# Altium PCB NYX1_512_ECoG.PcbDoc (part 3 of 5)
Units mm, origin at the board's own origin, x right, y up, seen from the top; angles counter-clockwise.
Board outline 46.64 x 13 mm, 4 copper layers (metal 2, via, metal1, electrodes), stack 0.007 mm thick; 9 components, 547 nets, 1871 pads, 0 vias.
Unrouted connection lines stored in the file: 652.
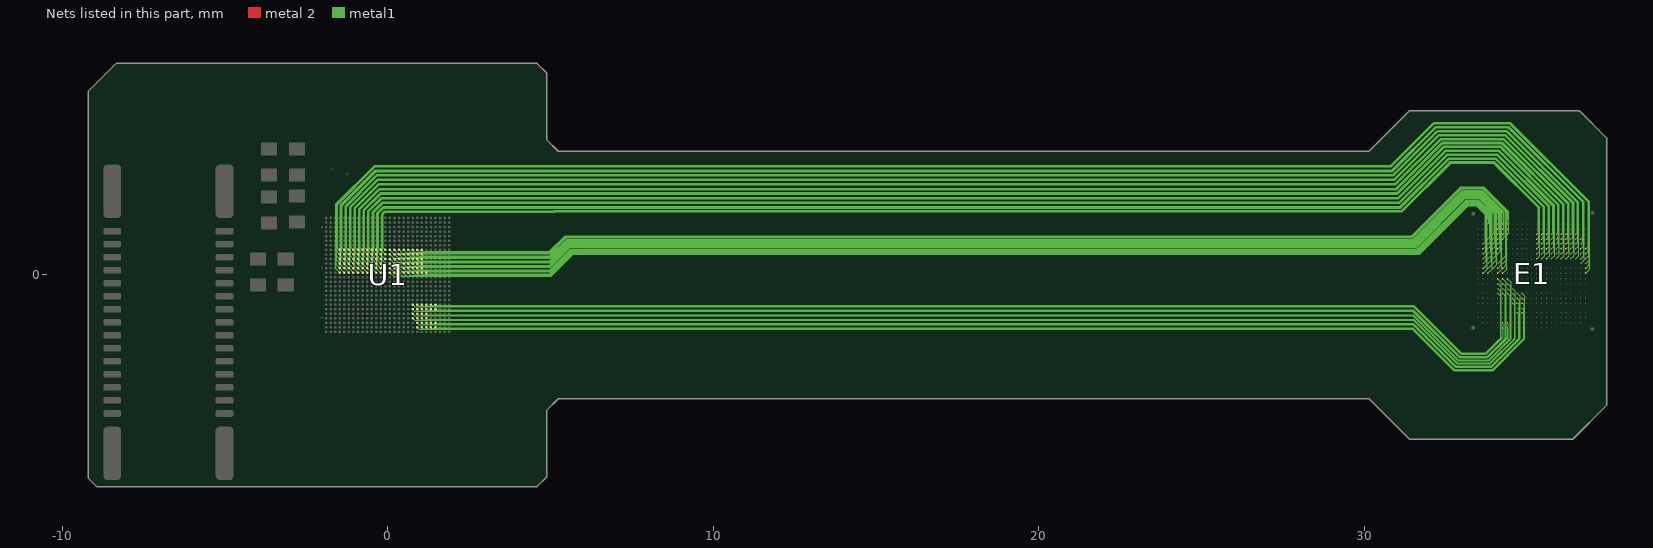
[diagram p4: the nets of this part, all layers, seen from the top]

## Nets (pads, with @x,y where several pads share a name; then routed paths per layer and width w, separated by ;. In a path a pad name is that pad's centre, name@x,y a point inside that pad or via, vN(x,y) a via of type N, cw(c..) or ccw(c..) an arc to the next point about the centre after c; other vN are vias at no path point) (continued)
el141: E1.21 pad.34@33.791,1.564 U1.F13 | length 34
  metal 2 w0.012: E1.21@33.791,1.544 pad.34@33.791,1.564
  metal1 w0.005: U1.F13@1.19,0.071 1.227,0.034 4.987,0.034 5.666,0.712 31.663,0.712 33.163,2.212 33.462,2.212 33.821,1.854 33.821,1.594 pad.34@33.791,1.564
el142: E1.70 pad.34@34.391,1.264 U1.G8 | length 35.3
  metal 2 w0.012: E1.70@34.391,1.244 pad.34@34.391,1.264
  metal1 w0.005: U1.G8@1.05,0.771 1.097,0.724 4.966,0.724 5.455,1.213 30.141,1.213 31.456,1.213 32.956,2.713 33.669,2.713 34.441,1.941 34.441,1.294 34.41,1.264 pad.34@34.391,1.264
el143: E1.92 pad.34@34.241,1.114 U1.G9 | length 35.3
  metal 2 w0.012: E1.92@34.241,1.094 pad.34@34.241,1.114
  metal1 w0.005: U1.G9@1.05,0.631 1.097,0.584 4.984,0.584 5.503,1.103 6.137,1.103 30.141,1.103 31.501,1.103 33.001,2.603 33.623,2.603 34.301,1.925 34.301,1.154 34.26,1.114 pad.34@34.241,1.114
el144: E1.160 pad.34@34.091,0.664 U1.G10 | length 35.6
  metal 2 w0.012: E1.160@34.091,0.644 pad.34@34.091,0.664
  metal1 w0.005: U1.G10@1.05,0.491 1.097,0.444 4.973,0.444 5.541,1.013 30.141,1.013 31.539,1.013 33.039,2.513 33.586,2.513 34.181,1.918 34.181,0.734 34.11,0.664 pad.34@34.091,0.664
el145: E1.228 pad.34@33.941,0.214 U1.G11 | length 35.9
  metal 2 w0.012: E1.228@33.941,0.194 pad.34@33.941,0.214
  metal1 w0.005: U1.G11@1.05,0.351 1.097,0.304 4.96,0.304 5.579,0.923 6.137,0.923 30.071,0.923 31.576,0.923 33.076,2.423 33.549,2.423 34.061,1.911 34.061,0.314 33.96,0.214 pad.34@33.941,0.214
el146: E1.250 pad.34@33.791,0.064 U1.G12 | length 35.9
  metal 2 w0.012: E1.250@33.791,0.044 pad.34@33.791,0.064
  metal1 w0.005: U1.G12@1.05,0.211 1.097,0.164 4.976,0.164 5.624,0.813 31.621,0.813 33.121,2.313 33.503,2.313 33.921,1.895 33.921,0.174 33.81,0.064 pad.34@33.791,0.064
el147: E1.1 pad.34@33.791,1.714 U1.G13 | length 34
  metal 2 w0.012: E1.1@33.791,1.694 pad.34@33.791,1.714
  metal1 w0.005: U1.G13@1.05,0.071 1.097,0.024 4.991,0.024 5.67,0.702 31.667,0.702 33.167,2.202 33.458,2.202 33.811,1.849 33.811,1.734 pad.34@33.791,1.714
el148: E1.47 pad.34@34.391,1.414 U1.H8 | length 35.3
  metal 2 w0.012: E1.47@34.391,1.394 pad.34@34.391,1.414
  metal1 w0.005: U1.H8@0.91,0.771 0.967,0.714 4.971,0.714 5.459,1.203 30.141,1.203 31.46,1.203 32.96,2.703 33.665,2.703 34.431,1.937 34.431,1.434 34.41,1.414 pad.34@34.391,1.414
el149: E1.69 pad.34@34.241,1.264 U1.H9 | length 35.2
  metal 2 w0.012: E1.69@34.241,1.244 pad.34@34.241,1.264
  metal1 w0.005: U1.H9@0.91,0.631 0.967,0.574 4.988,0.574 5.507,1.093 30.141,1.093 31.505,1.093 33.005,2.593 33.619,2.593 34.291,1.921 34.291,1.294 34.26,1.264 pad.34@34.241,1.264
el150: E1.137 pad.34@34.091,0.814 U1.H10 | length 35.5
  metal 2 w0.012: E1.137@34.091,0.794 pad.34@34.091,0.814
  metal1 w0.005: U1.H10@0.91,0.491 0.967,0.434 4.977,0.434 5.545,1.003 30.141,1.003 31.543,1.003 33.043,2.503 33.582,2.503 34.171,1.914 34.171,0.874 34.11,0.814 pad.34@34.091,0.814
el151: E1.205 pad.34@33.941,0.364 U1.H11 | length 35.9
  metal 2 w0.012: E1.205@33.941,0.344 pad.34@33.941,0.364
  metal1 w0.005: U1.H11@0.91,0.351 0.967,0.294 4.964,0.294 5.583,0.913 6.137,0.913 30.075,0.913 31.58,0.913 33.08,2.413 33.545,2.413 34.051,1.907 34.051,0.454 33.96,0.364 pad.34@33.941,0.364
el152: E1.227 pad.34@33.791,0.214 U1.H12 | length 35.8
  metal 2 w0.012: E1.227@33.791,0.194 pad.34@33.791,0.214
  metal1 w0.005: U1.H12@0.91,0.211 0.967,0.154 4.98,0.154 5.628,0.803 31.626,0.803 33.126,2.303 33.499,2.303 33.911,1.891 33.911,0.314 33.81,0.214 pad.34@33.791,0.214
el153: E1.249 pad.34@33.641,0.064 U1.H13 | length 35.8
  metal 2 w0.012: E1.249@33.641,0.044 pad.34@33.641,0.064
  metal1 w0.005: U1.H13@0.91,0.071 0.967,0.014 4.995,0.014 5.674,0.692 31.671,0.692 33.171,2.192 33.454,2.192 33.771,1.875 33.771,0.174 33.66,0.064 pad.34@33.641,0.064
el154: E1.25 pad.34@34.391,1.564 U1.J8 | length 35.2
  metal 2 w0.012: E1.25@34.391,1.544 pad.34@34.391,1.564
  metal1 w0.005: U1.J8@0.77,0.771 0.837,0.704 4.975,0.704 5.463,1.193 31.464,1.193 32.964,2.693 33.661,2.693 34.421,1.933 34.421,1.594 pad.34@34.391,1.564
el155: E1.46 pad.34@34.241,1.414 U1.J9 | length 35.2
  metal 2 w0.012: E1.46@34.241,1.394 pad.34@34.241,1.414
  metal1 w0.005: U1.J9@0.77,0.631 0.837,0.564 4.992,0.564 5.511,1.083 30.141,1.083 31.51,1.083 33.01,2.583 33.615,2.583 34.281,1.917 34.281,1.434 34.26,1.414 pad.34@34.241,1.414
el156: E1.114 pad.34@34.091,0.964 U1.J10 | length 35.5
  metal 2 w0.012: E1.114@34.091,0.944 pad.34@34.091,0.964
  metal1 w0.005: U1.J10@0.77,0.491 0.837,0.424 4.981,0.424 5.55,0.993 30.141,0.993 31.547,0.993 33.047,2.493 33.578,2.493 34.161,1.91 34.161,1.014 34.11,0.964 pad.34@34.091,0.964
el157: E1.182 pad.34@33.941,0.514 U1.J11 | length 35.8
  metal 2 w0.012: E1.182@33.941,0.494 pad.34@33.941,0.514
  metal1 w0.005: U1.J11@0.77,0.351 0.837,0.284 4.968,0.284 5.587,0.903 6.137,0.903 30.079,0.903 31.584,0.903 33.084,2.403 33.541,2.403 34.041,1.902 34.041,0.594 33.96,0.514 pad.34@33.941,0.514
el158: E1.204 pad.34@33.791,0.364 U1.J12 | length 35.8
  metal 2 w0.012: E1.204@33.791,0.344 pad.34@33.791,0.364
  metal1 w0.005: U1.J12@0.77,0.211 0.837,0.144 4.984,0.144 5.632,0.793 31.63,0.793 33.13,2.293 33.495,2.293 33.901,1.887 33.901,0.454 33.81,0.364 pad.34@33.791,0.364
el159: E1.226 pad.34@33.641,0.214 U1.J13 | length 35.8
  metal 2 w0.012: E1.226@33.641,0.194 pad.34@33.641,0.214
  metal1 w0.005: U1.J13@0.77,0.071 0.837,0.004 4.999,0.004 5.678,0.682 31.675,0.682 33.175,2.182 33.449,2.182 33.761,1.871 33.761,0.314 33.66,0.214 pad.34@33.641,0.214
el160: E1.5 pad.34@34.391,1.714 U1.K8 | length 35.2
  metal 2 w0.012: E1.5@34.391,1.694 pad.34@34.391,1.714
  metal1 w0.005: U1.K8@0.63,0.771 0.707,0.694 4.979,0.694 5.468,1.183 30.141,1.183 31.468,1.183 32.968,2.683 33.657,2.683 34.411,1.928 34.411,1.734 pad.34@34.391,1.714
el161: E1.24 pad.34@34.241,1.564 U1.K9 | length 35.2
  metal 2 w0.012: E1.24@34.241,1.544 pad.34@34.241,1.564
  metal1 w0.005: U1.K9@0.63,0.631 0.707,0.554 4.996,0.554 5.515,1.073 30.141,1.073 31.514,1.073 33.014,2.573 33.611,2.573 34.271,1.913 34.271,1.594 pad.34@34.241,1.564
el162: E1.91 pad.34@34.091,1.114 U1.K10 | length 35.5
  metal 2 w0.012: E1.91@34.091,1.094 pad.34@34.091,1.114
  metal1 w0.005: U1.K10@0.63,0.491 0.707,0.414 4.985,0.414 5.554,0.983 30.141,0.983 31.551,0.983 33.051,2.483 33.574,2.483 34.151,1.906 34.151,1.154 34.11,1.114 pad.34@34.091,1.114
el163: E1.159 pad.34@33.941,0.664 U1.K11 | length 35.8
  metal 2 w0.012: E1.159@33.941,0.644 pad.34@33.941,0.664
  metal1 w0.005: U1.K11@0.63,0.351 0.707,0.274 4.972,0.274 5.591,0.893 6.137,0.893 30.083,0.893 31.588,0.893 33.088,2.393 33.536,2.393 34.031,1.898 34.031,0.734 33.96,0.664 pad.34@33.941,0.664
el164: E1.181 pad.34@33.791,0.514 U1.K12 | length 35.8
  metal 2 w0.012: E1.181@33.791,0.494 pad.34@33.791,0.514
  metal1 w0.005: U1.K12@0.63,0.211 0.707,0.134 4.988,0.134 5.637,0.783 31.634,0.783 33.134,2.283 33.491,2.283 33.891,1.883 33.891,0.594 33.81,0.514 pad.34@33.791,0.514
el165: E1.203 pad.34@33.641,0.364 U1.K13 | length 35.8
  metal 2 w0.012: E1.203@33.641,0.344 pad.34@33.641,0.364
  metal1 w0.005: U1.K13@0.63,0.071 0.707,-0.006 5.004,-0.006 5.682,0.672 31.679,0.672 33.179,2.172 33.445,2.172 33.751,1.867 33.751,0.454 33.66,0.364 pad.34@33.641,0.364
el166: E1.253 pad.34@34.241,0.064 U1.L8 | length 37
  metal 2 w0.012: E1.253@34.241,0.044 pad.34@34.241,0.064
  metal1 w0.005: U1.L8@0.49,0.771 0.577,0.684 4.983,0.684 5.472,1.173 30.141,1.173 31.472,1.173 32.972,2.673 33.652,2.673 34.371,1.954 34.371,0.174 34.26,0.064 pad.34@34.241,0.064
el167: E1.4 pad.34@34.241,1.714 U1.L9 | length 35.1
  metal 2 w0.012: E1.4@34.241,1.694 pad.34@34.241,1.714
  metal1 w0.005: U1.L9@0.49,0.631 0.577,0.544 5.001,0.544 5.519,1.063 30.141,1.063 31.518,1.063 33.018,2.563 33.607,2.563 34.261,1.909 34.261,1.734 pad.34@34.241,1.714
el168: E1.68 pad.34@34.091,1.264 U1.L10 | length 35.5
  metal 2 w0.012: E1.68@34.091,1.244 pad.34@34.091,1.264
  metal1 w0.005: U1.L10@0.49,0.491 0.577,0.404 4.989,0.404 5.558,0.973 30.141,0.973 31.555,0.973 33.055,2.473 33.57,2.473 34.141,1.901 34.141,1.294 34.11,1.264 pad.34@34.091,1.264
el169: E1.136 pad.34@33.941,0.814 U1.L11 | length 35.8
  metal 2 w0.012: E1.136@33.941,0.794 pad.34@33.941,0.814
  metal1 w0.005: U1.L11@0.49,0.351 0.577,0.264 4.976,0.264 5.595,0.883 6.137,0.883 30.087,0.883 31.592,0.883 33.092,2.383 33.532,2.383 34.021,1.894 34.021,0.874 33.96,0.814 pad.34@33.941,0.814
el170: E1.158 pad.34@33.791,0.664 U1.L12 | length 35.8
  metal 2 w0.012: E1.158@33.791,0.644 pad.34@33.791,0.664
  metal1 w0.005: U1.L12@0.49,0.211 0.577,0.124 4.992,0.124 5.641,0.773 31.638,0.773 33.138,2.273 33.487,2.273 33.881,1.878 33.881,0.734 33.81,0.664 pad.34@33.791,0.664
el171: E1.180 pad.34@33.641,0.514 U1.L13 | length 35.7
  metal 2 w0.012: E1.180@33.641,0.494 pad.34@33.641,0.514
  metal1 w0.005: U1.L13@0.49,0.071 0.577,-0.016 5.008,-0.016 5.686,0.662 31.684,0.662 33.184,2.162 33.441,2.162 33.741,1.863 33.741,0.594 33.66,0.514 pad.34@33.641,0.514
el172: E1.230 pad.34@34.241,0.214 U1.M8 | length 37
  metal 2 w0.012: E1.230@34.241,0.194 pad.34@34.241,0.214
  metal1 w0.005: U1.M8@0.35,0.771 0.447,0.674 4.987,0.674 5.476,1.163 30.141,1.163 31.476,1.163 32.976,2.663 33.648,2.663 34.361,1.95 34.361,0.314 34.26,0.214 pad.34@34.241,0.214
el173: E1.252 pad.34@34.091,0.064 U1.M9 | length 37
  metal 2 w0.012: E1.252@34.091,0.044 pad.34@34.091,0.064
  metal1 w0.005: U1.M9@0.35,0.631 0.447,0.534 5.005,0.534 5.523,1.053 30.141,1.053 31.522,1.053 33.022,2.553 33.603,2.553 34.221,1.935 34.221,0.174 34.11,0.064 pad.34@34.091,0.064
el174: E1.45 pad.34@34.091,1.414 U1.M10 | length 35.4
  metal 2 w0.012: E1.45@34.091,1.394 pad.34@34.091,1.414
  metal1 w0.005: U1.M10@0.35,0.491 0.447,0.394 4.993,0.394 5.562,0.963 30.141,0.963 31.559,0.963 33.059,2.463 33.565,2.463 34.131,1.897 34.131,1.434 34.11,1.414 pad.34@34.091,1.414
el175: E1.113 pad.34@33.941,0.964 U1.M11 | length 35.8
  metal 2 w0.012: E1.113@33.941,0.944 pad.34@33.941,0.964
  metal1 w0.005: U1.M11@0.35,0.351 0.447,0.254 4.981,0.254 5.599,0.873 6.137,0.873 30.091,0.873 31.597,0.873 33.097,2.373 33.528,2.373 34.011,1.89 34.011,1.014 33.96,0.964 pad.34@33.941,0.964
el176: E1.135 pad.34@33.791,0.814 U1.M12 | length 35.7
  metal 2 w0.012: E1.135@33.791,0.794 pad.34@33.791,0.814
  metal1 w0.005: U1.M12@0.35,0.211 0.447,0.114 4.996,0.114 5.645,0.763 31.642,0.763 33.142,2.263 33.483,2.263 33.871,1.874 33.871,0.874 33.81,0.814 pad.34@33.791,0.814
el177: E1.157 pad.34@33.641,0.664 U1.M13 | length 35.7
  metal 2 w0.012: E1.157@33.641,0.644 pad.34@33.641,0.664
  metal1 w0.005: U1.M13@0.35,0.071 0.447,-0.026 5.012,-0.026 5.69,0.652 31.688,0.652 33.188,2.152 33.437,2.152 33.731,1.859 33.731,0.734 33.66,0.664 pad.34@33.641,0.664
el178: E1.207 pad.34@34.241,0.364 U1.N8 | length 37
  metal 2 w0.012: E1.207@34.241,0.344 pad.34@34.241,0.364
  metal1 w0.005: U1.N8@0.21,0.771 0.317,0.664 4.991,0.664 5.48,1.153 30.141,1.153 31.481,1.153 32.981,2.653 33.644,2.653 34.351,1.946 34.351,0.454 34.26,0.364 pad.34@34.241,0.364
el179: E1.229 pad.34@34.091,0.214 U1.N9 | length 36.9
  metal 2 w0.012: E1.229@34.091,0.194 pad.34@34.091,0.214
  metal1 w0.005: U1.N9@0.21,0.631 0.317,0.524 5.009,0.524 5.528,1.043 30.141,1.043 31.526,1.043 33.026,2.543 33.599,2.543 34.211,1.93 34.211,0.314 34.11,0.214 pad.34@34.091,0.214
el180: E1.23 pad.34@34.091,1.564 U1.N10 | length 35.4
  metal 2 w0.012: E1.23@34.091,1.544 pad.34@34.091,1.564
  metal1 w0.005: U1.N10@0.21,0.491 0.317,0.384 4.997,0.384 5.566,0.953 6.137,0.953 30.058,0.953 31.563,0.953 33.063,2.453 33.561,2.453 34.121,1.893 34.121,1.594 pad.34@34.091,1.564
el181: E1.90 pad.34@33.941,1.114 U1.N11 | length 35.7
  metal 2 w0.012: E1.90@33.941,1.094 pad.34@33.941,1.114
  metal1 w0.005: U1.N11@0.21,0.351 0.317,0.244 4.985,0.244 5.603,0.863 6.137,0.863 30.095,0.863 31.601,0.863 33.101,2.363 33.524,2.363 34.001,1.886 34.001,1.154 33.96,1.114 pad.34@33.941,1.114
el182: E1.112 pad.34@33.791,0.964 U1.N12 | length 35.7
  metal 2 w0.012: E1.112@33.791,0.944 pad.34@33.791,0.964
  metal1 w0.005: U1.N12@0.21,0.211 0.317,0.104 5,0.104 5.649,0.753 31.646,0.753 33.146,2.253 33.478,2.253 33.861,1.87 33.861,1.014 33.81,0.964 pad.34@33.791,0.964
el183: E1.134 pad.34@33.641,0.814 U1.N13 | length 35.7
  metal 2 w0.012: E1.134@33.641,0.794 pad.34@33.641,0.814
  metal1 w0.005: U1.N13@0.21,0.071 0.317,-0.036 5.016,-0.036 5.695,0.642 31.692,0.642 33.192,2.142 33.433,2.142 33.721,1.855 33.721,0.874 33.66,0.814 pad.34@33.641,0.814
el184: E1.184 pad.34@34.241,0.514 U1.P8 | length 36.9
  metal 2 w0.012: E1.184@34.241,0.494 pad.34@34.241,0.514
  metal1 w0.005: U1.P8@0.07,0.771 0.188,0.654 4.997,0.654 5.486,1.143 30.141,1.143 31.485,1.143 32.985,2.643 33.64,2.643 34.341,1.942 34.341,0.594 34.26,0.514 pad.34@34.241,0.514
el185: E1.206 pad.34@34.091,0.364 U1.P9 | length 36.9
  metal 2 w0.012: E1.206@34.091,0.344 pad.34@34.091,0.364
  metal1 w0.005: U1.P9@0.07,0.631 0.188,0.514 5.013,0.514 5.532,1.033 30.141,1.033 31.53,1.033 33.03,2.533 33.594,2.533 34.201,1.926 34.201,0.454 34.11,0.364 pad.34@34.091,0.364
el186: E1.3 pad.34@34.091,1.714 U1.P10 | length 35.4
  metal 2 w0.012: E1.3@34.091,1.694 pad.34@34.091,1.714
  metal1 w0.005: U1.P10@0.07,0.491 0.188,0.374 5.002,0.374 5.57,0.943 6.137,0.943 30.062,0.943 31.568,0.943 33.068,2.443 33.557,2.443 34.111,1.889 34.111,1.734 pad.34@34.091,1.714
el187: E1.67 pad.34@33.941,1.264 U1.P11 | length 35.7
  metal 2 w0.012: E1.67@33.941,1.244 pad.34@33.941,1.264
  metal1 w0.005: U1.P11@0.07,0.351 0.188,0.234 4.989,0.234 5.608,0.853 6.137,0.853 30.1,0.853 31.605,0.853 33.105,2.353 33.52,2.353 33.991,1.882 33.991,1.294 33.96,1.264 pad.34@33.941,1.264
el188: E1.89 pad.34@33.791,1.114 U1.P12 | length 35.7
  metal 2 w0.012: E1.89@33.791,1.094 pad.34@33.791,1.114
  metal1 w0.005: U1.P12@0.07,0.211 0.188,0.094 5.005,0.094 5.653,0.743 30.141,0.743 ; 30.145,0.743 31.65,0.743 33.15,2.243 33.474,2.243 33.851,1.866 33.851,1.154 33.81,1.114 pad.34@33.791,1.114
el189: E1.111 pad.34@33.641,0.964 U1.P13 | length 35.7
  metal 2 w0.012: E1.111@33.641,0.944 pad.34@33.641,0.964
  metal1 w0.005: U1.P13@0.07,0.071 0.188,-0.046 5.02,-0.046 5.699,0.632 31.696,0.632 33.196,2.132 33.429,2.132 33.711,1.85 33.711,1.014 33.66,0.964 pad.34@33.641,0.964
el190: E1.76 pad.34@35.291,1.264 U1.R8 | length 38.7
  metal 2 w0.012: E1.76@35.291,1.244 pad.34@35.291,1.264
  metal1 w0.005: U1.R8@-0.07,0.771 -0.138,0.839 -0.138,1.865 -0.079,1.924 5.14,1.924 5.153,1.936 30.141,1.936 31.161,1.936 32.661,3.436 33.964,3.436 35.341,2.059 35.341,1.294 35.31,1.264 pad.34@35.291,1.264
el191: E1.99 pad.34@35.291,1.114 U1.R9 | length 39
  metal 2 w0.012: E1.99@35.291,1.094 pad.34@35.291,1.114
  metal1 w0.005: U1.R9@-0.07,0.631 -0.148,0.709 -0.148,1.869 -0.083,1.934 5.136,1.934 5.149,1.946 30.137,1.946 31.157,1.946 32.657,3.446 33.968,3.446 35.351,2.063 35.351,1.154 35.31,1.114 pad.34@35.291,1.114
el192: E1.122 pad.34@35.291,0.964 U1.R10 | length 39.3
  metal 2 w0.012: E1.122@35.291,0.944 pad.34@35.291,0.964
  metal1 w0.005: U1.R10@-0.07,0.491 -0.158,0.579 -0.158,1.873 -0.087,1.944 5.132,1.944 5.144,1.956 30.133,1.956 31.153,1.956 32.653,3.456 33.972,3.456 35.361,2.068 35.361,1.014 35.31,0.964 pad.34@35.291,0.964
el193: E1.145 pad.34@35.291,0.814 U1.R11 | length 39.7
  metal 2 w0.012: E1.145@35.291,0.794 pad.34@35.291,0.814
  metal1 w0.005: U1.R11@-0.07,0.351 -0.168,0.449 -0.168,1.878 -0.091,1.954 5.128,1.954 5.14,1.966 30.129,1.966 31.149,1.966 32.649,3.466 33.976,3.466 35.371,2.072 35.371,0.874 35.31,0.814 pad.34@35.291,0.814
el194: E1.168 pad.34@35.291,0.664 U1.R12 | length 40
  metal 2 w0.012: E1.168@35.291,0.644 pad.34@35.291,0.664
  metal1 w0.005: U1.R12@-0.07,0.211 -0.178,0.319 -0.178,1.882 -0.095,1.964 5.124,1.964 5.136,1.976 30.124,1.976 31.144,1.976 32.644,3.476 33.98,3.476 35.381,2.076 35.381,0.734 35.31,0.664 pad.34@35.291,0.664
el195: E1.191 pad.34@35.291,0.514 U1.R13 | length 40.3
  metal 2 w0.012: E1.191@35.291,0.494 pad.34@35.291,0.514
  metal1 w0.005: U1.R13@-0.07,0.071 -0.188,0.189 -0.188,1.886 -0.099,1.974 5.12,1.974 5.132,1.986 30.12,1.986 31.14,1.986 32.64,3.486 33.984,3.486 35.391,2.08 35.391,0.594 35.31,0.514 pad.34@35.291,0.514
el196: E1.77 pad.34@35.441,1.264 U1.T8 | length 39.1
  metal 2 w0.012: E1.77@35.441,1.244 pad.34@35.441,1.264
  metal1 w0.005: U1.T8@-0.21,0.771 -0.278,0.839 -0.278,1.895 -0.115,2.057 30.141,2.057 31.112,2.057 32.612,3.557 34.013,3.557 35.491,2.079 35.491,1.294 35.46,1.264 pad.34@35.441,1.264
el197: E1.100 pad.34@35.441,1.114 U1.T9 | length 39.4
  metal 2 w0.012: E1.100@35.441,1.094 pad.34@35.441,1.114
  metal1 w0.005: U1.T9@-0.21,0.631 -0.288,0.709 -0.288,1.899 -0.119,2.067 30.141,2.067 31.108,2.067 32.608,3.567 34.017,3.567 35.501,2.083 35.501,1.154 35.46,1.114 pad.34@35.441,1.114
el198: E1.123 pad.34@35.441,0.964 U1.T10 | length 39.8
  metal 2 w0.012: E1.123@35.441,0.944 pad.34@35.441,0.964
  metal1 w0.005: U1.T10@-0.21,0.491 -0.298,0.579 -0.298,1.903 -0.123,2.077 30.141,2.077 31.104,2.077 32.604,3.577 34.021,3.577 35.511,2.087 35.511,1.014 35.46,0.964 pad.34@35.441,0.964
el199: E1.146 pad.34@35.441,0.814 U1.T11 | length 40.1
  metal 2 w0.012: E1.146@35.441,0.794 pad.34@35.441,0.814
  metal1 w0.005: U1.T11@-0.21,0.351 -0.308,0.449 -0.308,1.907 -0.127,2.087 30.141,2.087 31.1,2.087 32.6,3.587 34.025,3.587 35.521,2.092 35.521,0.874 35.46,0.814 pad.34@35.441,0.814
el200: E1.169 pad.34@35.441,0.664 U1.T12 | length 40.4
  metal 2 w0.012: E1.169@35.441,0.644 pad.34@35.441,0.664
  metal1 w0.005: U1.T12@-0.21,0.211 -0.318,0.319 -0.318,1.911 -0.132,2.097 30.141,2.097 31.096,2.097 32.596,3.597 34.029,3.597 35.531,2.096 35.531,0.734 35.46,0.664 pad.34@35.441,0.664
el201: E1.192 pad.34@35.441,0.514 U1.T13 | length 40.7
  metal 2 w0.012: E1.192@35.441,0.494 pad.34@35.441,0.514
  metal1 w0.005: U1.T13@-0.21,0.071 -0.328,0.189 -0.328,1.916 -0.136,2.107 30.141,2.107 31.092,2.107 32.591,3.607 34.033,3.607 35.541,2.1 35.541,0.594 35.46,0.514 pad.34@35.441,0.514
el202: E1.78 pad.34@35.591,1.264 U1.U8 | length 39.5
  metal 2 w0.012: E1.78@35.591,1.244 pad.34@35.591,1.264
  metal1 w0.005: U1.U8@-0.35,0.771 -0.418,0.839 -0.418,1.925 -0.138,2.204 31.089,2.204 32.562,3.677 34.062,3.677 35.641,2.099 35.641,1.294 35.61,1.264 pad.34@35.591,1.264
el203: E1.101 pad.34@35.591,1.114 U1.U9 | length 39.8
  metal 2 w0.012: E1.101@35.591,1.094 pad.34@35.591,1.114
  metal1 w0.005: U1.U9@-0.35,0.631 -0.428,0.709 -0.428,1.929 -0.142,2.214 31.085,2.214 32.558,3.687 34.066,3.687 35.651,2.103 35.651,1.154 35.61,1.114 pad.34@35.591,1.114
el204: E1.124 pad.34@35.591,0.964 U1.U10 | length 40.2
  metal 2 w0.012: E1.124@35.591,0.944 pad.34@35.591,0.964
  metal1 w0.005: U1.U10@-0.35,0.491 -0.438,0.579 -0.438,1.933 -0.147,2.224 31.081,2.224 32.554,3.697 34.071,3.697 35.661,2.107 35.661,1.014 35.61,0.964 pad.34@35.591,0.964
el205: E1.147 pad.34@35.591,0.814 U1.U11 | length 40.5
  metal 2 w0.012: E1.147@35.591,0.794 pad.34@35.591,0.814
  metal1 w0.005: U1.U11@-0.35,0.351 -0.448,0.449 -0.448,1.937 -0.151,2.234 31.077,2.234 32.55,3.707 34.075,3.707 35.671,2.111 35.671,0.874 35.61,0.814 pad.34@35.591,0.814
el206: E1.170 pad.34@35.591,0.664 U1.U12 | length 40.8
  metal 2 w0.012: E1.170@35.591,0.644 pad.34@35.591,0.664
  metal1 w0.005: U1.U12@-0.35,0.211 -0.458,0.319 -0.458,1.941 -0.155,2.244 31.073,2.244 32.546,3.717 34.079,3.717 35.681,2.115 35.681,0.734 35.61,0.664 pad.34@35.591,0.664
el207: E1.193 pad.34@35.591,0.514 U1.U13 | length 41.2
  metal 2 w0.012: E1.193@35.591,0.494 pad.34@35.591,0.514
  metal1 w0.005: U1.U13@-0.35,0.071 -0.468,0.189 -0.468,1.945 -0.159,2.254 31.068,2.254 32.542,3.727 34.083,3.727 35.691,2.12 35.691,0.594 35.61,0.514 pad.34@35.591,0.514
el208: E1.79 pad.34@35.741,1.264 U1.V8 | length 39.9
  metal 2 w0.012: E1.79@35.741,1.244 pad.34@35.741,1.264
  metal1 w0.005: U1.V8@-0.49,0.771 -0.558,0.839 -0.558,1.954 -0.168,2.344 30.141,2.344 31.059,2.344 32.513,3.797 34.112,3.797 35.791,2.119 35.791,1.294 35.76,1.264 pad.34@35.741,1.264
el209: E1.102 pad.34@35.741,1.114 U1.V9 | length 40.3
  metal 2 w0.012: E1.102@35.741,1.094 pad.34@35.741,1.114
  metal1 w0.005: U1.V9@-0.49,0.631 -0.568,0.709 -0.568,1.959 -0.172,2.354 30.141,2.354 31.055,2.354 32.509,3.807 34.116,3.807 35.801,2.123 35.801,1.154 35.76,1.114 pad.34@35.741,1.114
el210: E1.125 pad.34@35.741,0.964 U1.V10 | length 40.6
  metal 2 w0.012: E1.125@35.741,0.944 pad.34@35.741,0.964
  metal1 w0.005: U1.V10@-0.49,0.491 -0.578,0.579 -0.578,1.963 -0.176,2.364 30.141,2.364 31.051,2.364 32.504,3.817 34.12,3.817 35.811,2.127 35.811,1.014 35.76,0.964 pad.34@35.741,0.964
el211: E1.148 pad.34@35.741,0.814 U1.V11 | length 40.9
  metal 2 w0.012: E1.148@35.741,0.794 pad.34@35.741,0.814
  metal1 w0.005: U1.V11@-0.49,0.351 -0.588,0.449 -0.588,1.967 -0.18,2.374 30.141,2.374 31.047,2.374 32.5,3.827 34.124,3.827 35.821,2.131 35.821,0.874 35.76,0.814 pad.34@35.741,0.814
el212: E1.171 pad.34@35.741,0.664 U1.V12 | length 41.2
  metal 2 w0.012: E1.171@35.741,0.644 pad.34@35.741,0.664
  metal1 w0.005: U1.V12@-0.49,0.211 -0.598,0.319 -0.598,1.971 -0.185,2.384 30.141,2.384 31.043,2.384 32.496,3.837 34.129,3.837 35.831,2.135 35.831,0.734 35.76,0.664 pad.34@35.741,0.664
el213: E1.194 pad.34@35.741,0.514 U1.V13 | length 41.6
  metal 2 w0.012: E1.194@35.741,0.494 pad.34@35.741,0.514
  metal1 w0.005: U1.V13@-0.49,0.071 -0.608,0.189 -0.608,1.975 -0.189,2.394 30.141,2.394 31.039,2.394 32.492,3.847 34.133,3.847 35.841,2.139 35.841,0.594 35.76,0.514 pad.34@35.741,0.514
el214: E1.80 pad.34@35.891,1.264 U1.W8 | length 40.3
  metal 2 w0.012: E1.80@35.891,1.244 pad.34@35.891,1.264
  metal1 w0.005: U1.W8@-0.63,0.771 -0.698,0.839 -0.698,1.984 -0.198,2.484 30.141,2.484 31.03,2.484 32.463,3.917 34.162,3.917 35.941,2.138 35.941,1.294 35.91,1.264 pad.34@35.891,1.264
el215: E1.103 pad.34@35.891,1.114 U1.W9 | length 40.7
  metal 2 w0.012: E1.103@35.891,1.094 pad.34@35.891,1.114
  metal1 w0.005: U1.W9@-0.63,0.631 -0.708,0.709 -0.708,1.988 -0.202,2.494 30.141,2.494 31.025,2.494 32.459,3.927 34.166,3.927 35.951,2.142 35.951,1.154 35.91,1.114 pad.34@35.891,1.114
el216: E1.126 pad.34@35.891,0.964 U1.W10 | length 41
  metal 2 w0.012: E1.126@35.891,0.944 pad.34@35.891,0.964
  metal1 w0.005: U1.W10@-0.63,0.491 -0.718,0.579 -0.718,1.992 -0.206,2.504 31.021,2.504 32.455,3.937 34.17,3.937 35.961,2.147 35.961,1.014 35.91,0.964 pad.34@35.891,0.964
el217: E1.149 pad.34@35.891,0.814 U1.W11 | length 41.3
  metal 2 w0.012: E1.149@35.891,0.794 pad.34@35.891,0.814
  metal1 w0.005: U1.W11@-0.63,0.351 -0.728,0.449 -0.728,1.997 -0.21,2.514 31.017,2.514 32.451,3.947 34.174,3.947 35.971,2.151 35.971,0.874 35.91,0.814 pad.34@35.891,0.814
el218: E1.172 pad.34@35.891,0.664 U1.W12 | length 41.7
  metal 2 w0.012: E1.172@35.891,0.644 pad.34@35.891,0.664
  metal1 w0.005: U1.W12@-0.63,0.211 -0.738,0.319 -0.738,2.001 -0.214,2.524 31.013,2.524 32.446,3.957 34.178,3.957 35.981,2.155 35.981,0.734 35.91,0.664 pad.34@35.891,0.664
el219: E1.195 pad.34@35.891,0.514 U1.W13 | length 42
  metal 2 w0.012: E1.195@35.891,0.494 pad.34@35.891,0.514
  metal1 w0.005: U1.W13@-0.63,0.071 -0.748,0.189 -0.748,2.005 -0.218,2.534 31.009,2.534 32.442,3.967 34.182,3.967 35.991,2.159 35.991,0.594 35.91,0.514 pad.34@35.891,0.514
el220: E1.81 pad.34@36.041,1.264 U1.Y8 | length 40.8
  metal 2 w0.012: E1.81@36.041,1.244 pad.34@36.041,1.264
  metal1 w0.005: U1.Y8@-0.77,0.771 -0.838,0.839 -0.838,2.014 -0.237,2.614 30.141,2.614 30.99,2.614 32.413,4.037 34.211,4.037 36.091,2.158 36.091,1.294 36.06,1.264 pad.34@36.041,1.264
el221: E1.104 pad.34@36.041,1.114 U1.Y9 | length 41.1
  metal 2 w0.012: E1.104@36.041,1.094 pad.34@36.041,1.114
  metal1 w0.005: U1.Y9@-0.77,0.631 -0.848,0.709 -0.848,2.018 -0.241,2.624 30.141,2.624 30.986,2.624 32.409,4.047 34.216,4.047 36.101,2.162 36.101,1.154 36.06,1.114 pad.34@36.041,1.114
el222: E1.127 pad.34@36.041,0.964 U1.Y10 | length 41.4
  metal 2 w0.012: E1.127@36.041,0.944 pad.34@36.041,0.964
  metal1 w0.005: U1.Y10@-0.77,0.491 -0.858,0.579 -0.858,2.022 -0.245,2.634 30.141,2.634 30.982,2.634 32.405,4.057 34.22,4.057 36.111,2.166 36.111,1.014 36.06,0.964 pad.34@36.041,0.964
el223: E1.150 pad.34@36.041,0.814 U1.Y11 | length 41.8
  metal 2 w0.012: E1.150@36.041,0.794 pad.34@36.041,0.814
  metal1 w0.005: U1.Y11@-0.77,0.351 -0.868,0.449 -0.868,2.026 -0.249,2.644 30.141,2.644 30.978,2.644 32.401,4.067 34.224,4.067 36.121,2.17 36.121,0.874 36.06,0.814 pad.34@36.041,0.814
el224: E1.173 pad.34@36.041,0.664 U1.Y12 | length 42.1
  metal 2 w0.012: E1.173@36.041,0.644 pad.34@36.041,0.664
  metal1 w0.005: U1.Y12@-0.77,0.211 -0.878,0.319 -0.878,2.03 -0.254,2.654 30.141,2.654 30.974,2.654 32.396,4.077 34.228,4.077 36.131,2.175 36.131,0.734 36.06,0.664 pad.34@36.041,0.664
el225: E1.196 pad.34@36.041,0.514 U1.Y13 | length 42.4
  metal 2 w0.012: E1.196@36.041,0.494 pad.34@36.041,0.514
  metal1 w0.005: U1.Y13@-0.77,0.071 -0.888,0.189 -0.888,2.035 -0.258,2.664 30.141,2.664 30.969,2.664 32.392,4.087 34.232,4.087 36.141,2.179 36.141,0.594 36.06,0.514 pad.34@36.041,0.514
el226: E1.82 pad.34@36.191,1.264 U1.AA8 | length 41.2
  metal 2 w0.012: E1.82@36.191,1.244 pad.34@36.191,1.264
  metal1 w0.005: U1.AA8@-0.91,0.771 -0.978,0.839 -0.978,2.044 -0.257,2.764 30.141,2.764 30.97,2.764 32.363,4.157 34.261,4.157 36.241,2.178 36.241,1.294 36.21,1.264 pad.34@36.191,1.264
el227: E1.105 pad.34@36.191,1.114 U1.AA9 | length 41.5
  metal 2 w0.012: E1.105@36.191,1.094 pad.34@36.191,1.114
  metal1 w0.005: U1.AA9@-0.91,0.631 -0.988,0.709 -0.988,2.048 -0.261,2.774 30.141,2.774 30.966,2.774 32.359,4.167 34.265,4.167 36.251,2.182 36.251,1.154 36.21,1.114 pad.34@36.191,1.114
el228: E1.128 pad.34@36.191,0.964 U1.AA10 | length 41.8
  metal 2 w0.012: E1.128@36.191,0.944 pad.34@36.191,0.964
  metal1 w0.005: U1.AA10@-0.91,0.491 -0.998,0.579 -0.998,2.052 -0.265,2.784 30.141,2.784 30.962,2.784 32.355,4.177 34.269,4.177 36.261,2.186 36.261,1.014 36.21,0.964 pad.34@36.191,0.964
el229: E1.151 pad.34@36.191,0.814 U1.AA11 | length 42.2
  metal 2 w0.012: E1.151@36.191,0.794 pad.34@36.191,0.814
  metal1 w0.005: U1.AA11@-0.91,0.351 -1.008,0.449 -1.008,2.056 -0.27,2.794 30.141,2.794 30.957,2.794 32.351,4.187 34.274,4.187 36.271,2.19 36.271,0.874 36.21,0.814 pad.34@36.191,0.814
el230: E1.174 pad.34@36.191,0.664 U1.AA12 | length 42.5
  metal 2 w0.012: E1.174@36.191,0.644 pad.34@36.191,0.664
  metal1 w0.005: U1.AA12@-0.91,0.211 -1.018,0.319 -1.018,2.06 -0.274,2.804 30.141,2.804 30.953,2.804 32.347,4.197 34.278,4.197 36.281,2.194 36.281,0.734 36.21,0.664 pad.34@36.191,0.664
el231: E1.197 pad.34@36.191,0.514 U1.AA13 | length 42.8
  metal 2 w0.012: E1.197@36.191,0.494 pad.34@36.191,0.514
  metal1 w0.005: U1.AA13@-0.91,0.071 -1.028,0.189 -1.028,2.064 -0.278,2.814 30.949,2.814 32.343,4.207 34.282,4.207 36.291,2.199 36.291,0.594 36.21,0.514 pad.34@36.191,0.514
el232: E1.83 pad.34@36.341,1.264 U1.AB8 | length 41.6
  metal 2 w0.012: E1.83@36.341,1.244 pad.34@36.341,1.264
  metal1 w0.005: U1.AB8@-1.05,0.771 -1.118,0.839 -1.118,2.073 -0.287,2.904 30.141,2.904 30.931,2.904 32.304,4.277 34.311,4.277 36.391,2.198 36.391,1.294 36.36,1.264 pad.34@36.341,1.264
el233: E1.106 pad.34@36.341,1.114 U1.AB9 | length 41.9
  metal 2 w0.012: E1.106@36.341,1.094 pad.34@36.341,1.114
  metal1 w0.005: U1.AB9@-1.05,0.631 -1.128,0.709 -1.128,2.077 -0.291,2.914 30.141,2.914 30.927,2.914 32.3,4.287 34.315,4.287 36.401,2.202 36.401,1.154 36.36,1.114 pad.34@36.341,1.114
el234: E1.129 pad.34@36.341,0.964 U1.AB10 | length 42.3
  metal 2 w0.012: E1.129@36.341,0.944 pad.34@36.341,0.964
  metal1 w0.005: U1.AB10@-1.05,0.491 -1.138,0.579 -1.138,2.082 -0.295,2.924 30.922,2.924 32.296,4.297 34.319,4.297 36.411,2.206 36.411,1.014 36.36,0.964 pad.34@36.341,0.964
el235: E1.152 pad.34@36.341,0.814 U1.AB11 | length 42.6
  metal 2 w0.012: E1.152@36.341,0.794 pad.34@36.341,0.814
  metal1 w0.005: U1.AB11@-1.05,0.351 -1.148,0.449 -1.148,2.086 -0.299,2.934 30.918,2.934 32.292,4.307 34.323,4.307 36.421,2.21 36.421,0.874 36.36,0.814 pad.34@36.341,0.814
el236: E1.175 pad.34@36.341,0.664 U1.AB12 | length 42.9
  metal 2 w0.012: E1.175@36.341,0.644 pad.34@36.341,0.664
  metal1 w0.005: U1.AB12@-1.05,0.211 -1.158,0.319 -1.158,2.09 -0.304,2.944 30.914,2.944 32.288,4.317 34.327,4.317 36.431,2.214 36.431,0.734 36.36,0.664 pad.34@36.341,0.664
el237: E1.198 pad.34@36.341,0.514 U1.AB13 | length 43.3
  metal 2 w0.012: E1.198@36.341,0.494 pad.34@36.341,0.514
  metal1 w0.005: U1.AB13@-1.05,0.071 -1.168,0.189 -1.168,2.094 -0.308,2.954 30.91,2.954 32.284,4.327 34.332,4.327 36.441,2.218 36.441,0.594 36.36,0.514 pad.34@36.341,0.514
el238: E1.84 pad.34@36.491,1.264 U1.AC8 | length 42
  metal 2 w0.012: E1.84@36.491,1.244 pad.34@36.491,1.264
  metal1 w0.005: U1.AC8@-1.19,0.771 -1.258,0.839 -1.258,2.103 -0.317,3.044 0.437,3.044 30.141,3.044 30.901,3.044 32.257,4.4 34.358,4.4 36.541,2.217 36.541,1.294 36.51,1.264 pad.34@36.491,1.264
el239: E1.107 pad.34@36.491,1.114 U1.AC9 | length 42.4
  metal 2 w0.012: E1.107@36.491,1.094 pad.34@36.491,1.114
  metal1 w0.005: U1.AC9@-1.19,0.631 -1.268,0.709 -1.268,2.107 -0.321,3.054 30.141,3.054 30.897,3.054 32.253,4.41 34.362,4.41 36.551,2.221 36.551,1.154 36.51,1.114 pad.34@36.491,1.114
el240: E1.130 pad.34@36.491,0.964 U1.AC10 | length 42.7
  metal 2 w0.012: E1.130@36.491,0.944 pad.34@36.491,0.964
  metal1 w0.005: U1.AC10@-1.19,0.491 -1.278,0.579 -1.278,2.111 -0.325,3.064 30.141,3.064 30.893,3.064 32.249,4.42 34.366,4.42 36.561,2.226 36.561,1.014 36.51,0.964 pad.34@36.491,0.964
el241: E1.153 pad.34@36.491,0.814 U1.AC11 | length 43
  metal 2 w0.012: E1.153@36.491,0.794 pad.34@36.491,0.814
  metal1 w0.005: U1.AC11@-1.19,0.351 -1.288,0.449 -1.288,2.116 -0.329,3.074 30.141,3.074 30.889,3.074 32.245,4.43 34.37,4.43 36.571,2.23 36.571,0.874 36.51,0.814 pad.34@36.491,0.814
el242: E1.176 pad.34@36.491,0.664 U1.AC12 | length 43.3
  metal 2 w0.012: E1.176@36.491,0.644 pad.34@36.491,0.664
  metal1 w0.005: U1.AC12@-1.19,0.211 -1.298,0.319 -1.298,2.12 -0.333,3.084 30.141,3.084 30.884,3.084 32.241,4.44 34.374,4.44 36.581,2.234 36.581,0.734 36.51,0.664 pad.34@36.491,0.664
el243: E1.199 pad.34@36.491,0.514 U1.AC13 | length 43.7
  metal 2 w0.012: E1.199@36.491,0.494 pad.34@36.491,0.514
  metal1 w0.005: U1.AC13@-1.19,0.071 -1.308,0.189 -1.308,2.124 -0.337,3.094 30.141,3.094 30.88,3.094 32.237,4.45 34.378,4.45 36.591,2.238 36.591,0.594 36.51,0.514 pad.34@36.491,0.514
el244: E1.108 pad.34@36.641,1.114 U1.AD8 | length 42.6
  metal 2 w0.012: E1.108@36.641,1.094 pad.34@36.641,1.114
  metal1 w0.005: U1.AD8@-1.33,0.771 -1.398,0.839 -1.398,1.468 -1.4,1.47 -1.4,2.131 -0.352,3.178 30.141,3.178 30.866,3.178 32.208,4.52 34.407,4.52 36.701,2.227 36.701,1.154 36.66,1.114 pad.34@36.641,1.114
el245: E1.131 pad.34@36.641,0.964 U1.AD9 | length 42.9
  metal 2 w0.012: E1.131@36.641,0.944 pad.34@36.641,0.964
  metal1 w0.005: U1.AD9@-1.33,0.631 -1.408,0.709 -1.408,1.464 -1.41,1.466 -1.41,2.135 -0.356,3.188 30.141,3.188 30.862,3.188 32.204,4.53 34.412,4.53 36.711,2.231 36.711,1.014 36.66,0.964 pad.34@36.641,0.964
el246: E1.154 pad.34@36.641,0.814 U1.AD10 | length 43.3
  metal 2 w0.012: E1.154@36.641,0.794 pad.34@36.641,0.814
  metal1 w0.005: U1.AD10@-1.33,0.491 -1.418,0.579 -1.418,1.46 -1.42,1.462 -1.42,2.139 -0.36,3.198 30.141,3.198 30.857,3.198 32.199,4.54 34.416,4.54 36.721,2.235 36.721,0.874 36.66,0.814 pad.34@36.641,0.814
el247: E1.177 pad.34@36.641,0.664 U1.AD11 | length 43.6
  metal 2 w0.012: E1.177@36.641,0.644 pad.34@36.641,0.664
  metal1 w0.005: U1.AD11@-1.33,0.351 -1.428,0.449 -1.428,1.456 -1.43,1.458 -1.43,2.143 -0.364,3.208 30.141,3.208 30.853,3.208 32.195,4.55 34.42,4.55 36.731,2.239 36.731,0.734 36.66,0.664 pad.34@36.641,0.664
el248: E1.200 pad.34@36.641,0.514 U1.AD12 | length 43.9
  metal 2 w0.012: E1.200@36.641,0.494 pad.34@36.641,0.514
  metal1 w0.005: U1.AD12@-1.33,0.211 -1.438,0.319 -1.438,1.452 -1.44,1.454 -1.44,2.147 -0.369,3.218 30.141,3.218 30.849,3.218 32.191,4.56 34.424,4.56 36.741,2.244 36.741,0.594 36.66,0.514 pad.34@36.641,0.514
el249: E1.223 pad.34@36.641,0.364 U1.AD13 | length 44.3
  metal 2 w0.012: E1.223@36.641,0.344 pad.34@36.641,0.364
  metal1 w0.005: U1.AD13@-1.33,0.071 -1.448,0.189 -1.448,1.448 -1.45,1.45 -1.45,2.152 -0.373,3.228 30.845,3.228 32.187,4.57 34.428,4.57 36.751,2.248 36.751,0.454 36.66,0.364 pad.34@36.641,0.364
el250: E1.155 pad.34@36.791,0.814 U1.AE8 | length 43.3
  metal 2 w0.012: E1.155@36.791,0.794 pad.34@36.791,0.814
  metal1 w0.005: U1.AE8@-1.47,0.771 -1.538,0.839 -1.538,2.163 -0.376,3.324 30.141,3.324 30.83,3.324 32.146,4.64 34.457,4.64 36.871,2.227 36.871,0.874 36.81,0.814 pad.34@36.791,0.814
el251: E1.178 pad.34@36.791,0.664 U1.AE9 | length 43.7
  metal 2 w0.012: E1.178@36.791,0.644 pad.34@36.791,0.664
  metal1 w0.005: U1.AE9@-1.47,0.631 -1.548,0.709 -1.548,2.167 -0.38,3.334 30.141,3.334 30.826,3.334 32.142,4.65 34.461,4.65 36.881,2.231 36.881,0.734 36.81,0.664 pad.34@36.791,0.664
el252: E1.201 pad.34@36.791,0.514 U1.AE10 | length 44
  metal 2 w0.012: E1.201@36.791,0.494 pad.34@36.791,0.514
  metal1 w0.005: U1.AE10@-1.47,0.491 -1.558,0.579 -1.558,2.171 -0.384,3.344 30.141,3.344 30.822,3.344 32.138,4.66 34.465,4.66 36.891,2.235 36.891,0.594 36.81,0.514 pad.34@36.791,0.514
el253: E1.224 pad.34@36.791,0.364 U1.AE11 | length 44.3
  metal 2 w0.012: E1.224@36.791,0.344 pad.34@36.791,0.364
  metal1 w0.005: U1.AE11@-1.47,0.351 -1.568,0.449 -1.568,2.175 -0.389,3.354 0.437,3.354 ; 0.441,3.354 30.141,3.354 30.817,3.354 32.134,4.67 34.47,4.67 36.901,2.239 36.901,0.454 36.81,0.364 pad.34@36.791,0.364
el254: E1.247 pad.34@36.791,0.214 U1.AE12 | length 44.7
  metal 2 w0.012: E1.247@36.791,0.194 pad.34@36.791,0.214
  metal1 w0.005: U1.AE12@-1.47,0.211 -1.578,0.319 -1.578,2.179 -0.393,3.364 0.437,3.364 ; 0.441,3.364 30.813,3.364 32.13,4.68 34.474,4.68 36.911,2.243 36.911,0.314 36.81,0.214 pad.34@36.791,0.214
el255: E1.270 pad.34@36.791,0.064 U1.AE13 | length 45
  metal 2 w0.012: E1.270@36.791,0.044 pad.34@36.791,0.064
  metal1 w0.005: U1.AE13@-1.47,0.071 -1.588,0.189 -1.588,2.183 -0.397,3.374 0.437,3.374 ; 0.441,3.374 30.809,3.374 32.126,4.69 34.478,4.69 36.921,2.247 36.921,0.174 36.81,0.064 pad.34@36.791,0.064
el256: E1.344 pad.34@34.091,-0.575 U1.D20 | length 34.9
  metal 2 w0.012: pad.34@34.091,-0.575 E1.344@34.091,-0.556
  metal1 w0.005: U1.D20@1.47,-0.909 1.487,-0.926 3.141,-0.926 30.141,-0.926 31.515,-0.926 32.975,-2.386 33.73,-2.386 34.181,-1.935 34.181,-0.646 34.11,-0.575 pad.34@34.091,-0.575
el257: E1.345 pad.34@34.241,-0.575 U1.D21 | length 35.1
  metal 2 w0.012: pad.34@34.241,-0.575 E1.345@34.241,-0.556
  metal1 w0.005: U1.D21@1.47,-1.049 1.487,-1.066 31.499,-1.066 32.929,-2.496 33.775,-2.496 34.331,-1.941 34.331,-0.646 34.26,-0.575 pad.34@34.241,-0.575
el258: E1.440 pad.34@34.691,-1.175 U1.D24 | length 35
  metal 2 w0.012: pad.34@34.691,-1.175 E1.440@34.691,-1.156
  metal1 w0.005: U1.D24@1.47,-1.469 1.487,-1.486 3.141,-1.486 31.507,-1.486 32.808,-2.786 33.896,-2.786 34.741,-1.941 34.741,-1.206 34.71,-1.175 pad.34@34.691,-1.175
el259: E1.441 pad.34@34.841,-1.175 U1.D25 | length 35.2
  metal 2 w0.012: pad.34@34.841,-1.175 E1.441@34.841,-1.156
  metal1 w0.005: U1.D25@1.47,-1.609 1.487,-1.626 3.141,-1.626 31.491,-1.626 32.761,-2.896 33.941,-2.896 34.891,-1.947 34.891,-1.206 34.86,-1.175 pad.34@34.841,-1.175
el260: E1.321 pad.34@34.091,-0.425 U1.E20 | length 35.3
  metal 2 w0.012: pad.34@34.091,-0.425 E1.321@34.091,-0.406
  metal1 w0.005: U1.E20@1.33,-0.909 1.357,-0.936 3.141,-0.936 30.141,-0.936 31.51,-0.936 32.971,-2.396 33.734,-2.396 34.191,-1.939 34.191,-0.506 34.11,-0.425 pad.34@34.091,-0.425
el261: E1.322 pad.34@34.241,-0.425 U1.E21 | length 35.4
  metal 2 w0.012: pad.34@34.241,-0.425 E1.322@34.241,-0.406
  metal1 w0.005: U1.E21@1.33,-1.049 1.357,-1.076 31.495,-1.076 32.925,-2.506 33.78,-2.506 34.341,-1.945 34.341,-0.506 34.26,-0.425 pad.34@34.241,-0.425
el262: E1.417 pad.34@34.691,-1.025 U1.E24 | length 35.3
  metal 2 w0.012: pad.34@34.691,-1.025 E1.417@34.691,-1.006
  metal1 w0.005: U1.E24@1.33,-1.469 1.357,-1.496 3.141,-1.496 30.141,-1.496 31.503,-1.496 32.803,-2.796 33.9,-2.796 34.751,-1.945 34.751,-1.066 34.71,-1.025 pad.34@34.691,-1.025
el263: E1.418 pad.34@34.841,-1.025 U1.E25 | length 35.5
  metal 2 w0.012: pad.34@34.841,-1.025 E1.418@34.841,-1.006
  metal1 w0.005: U1.E25@1.33,-1.609 1.357,-1.636 3.141,-1.636 31.487,-1.636 32.757,-2.906 33.945,-2.906 34.901,-1.951 34.901,-1.066 34.86,-1.025 pad.34@34.841,-1.025
el264: E1.298 pad.34@34.091,-0.275 U1.F20 | length 35.6
  metal 2 w0.012: pad.34@34.091,-0.275 E1.298@34.091,-0.256
  metal1 w0.005: U1.F20@1.19,-0.909 1.227,-0.946 3.141,-0.946 31.506,-0.946 32.966,-2.406 33.738,-2.406 34.201,-1.943 34.201,-0.366 34.11,-0.275 pad.34@34.091,-0.275
el265: E1.299 pad.34@34.241,-0.275 U1.F21 | length 35.8
  metal 2 w0.012: pad.34@34.241,-0.275 E1.299@34.241,-0.256
  metal1 w0.005: U1.F21@1.19,-1.049 1.227,-1.086 31.491,-1.086 32.921,-2.516 33.784,-2.516 34.351,-1.949 34.351,-0.366 34.26,-0.275 pad.34@34.241,-0.275
el266: E1.346 pad.34@34.391,-0.575 U1.F22 | length 35.6
  metal 2 w0.012: pad.34@34.391,-0.575 E1.346@34.391,-0.556
  metal1 w0.005: U1.F22@1.19,-1.189 1.227,-1.226 3.141,-1.226 ; 3.145,-1.226 30.141,-1.226 31.502,-1.226 32.882,-2.606 33.821,-2.606 34.481,-1.946 34.481,-0.646 34.41,-0.575 pad.34@34.391,-0.575
el267: E1.393 pad.34@34.541,-0.875 U1.F23 | length 35.4
  metal 2 w0.012: pad.34@34.541,-0.875 E1.393@34.541,-0.856
  metal1 w0.005: U1.F23@1.19,-1.329 1.227,-1.366 31.515,-1.366 32.845,-2.696 33.858,-2.696 34.611,-1.944 34.611,-0.926 34.56,-0.875 pad.34@34.541,-0.875
el268: E1.394 pad.34@34.691,-0.875 U1.F24 | length 35.6
  metal 2 w0.012: pad.34@34.691,-0.875 E1.394@34.691,-0.856
  metal1 w0.005: U1.F24@1.19,-1.469 1.227,-1.506 3.141,-1.506 30.141,-1.506 31.499,-1.506 32.799,-2.806 33.904,-2.806 34.761,-1.949 34.761,-0.926 34.71,-0.875 pad.34@34.691,-0.875
el269: E1.395 pad.34@34.841,-0.875 U1.F25 | length 35.8
  metal 2 w0.012: pad.34@34.841,-0.875 E1.395@34.841,-0.856
  metal1 w0.005: U1.F25@1.19,-1.609 1.227,-1.646 30.141,-1.646 31.481,-1.646 32.751,-2.916 33.949,-2.916 34.911,-1.955 34.911,-0.926 34.86,-0.875 pad.34@34.841,-0.875
el270: E1.275 pad.34@34.091,-0.125 U1.G20 | length 35.9
  metal 2 w0.012: pad.34@34.091,-0.125 E1.275@34.091,-0.106
  metal1 w0.005: U1.G20@1.05,-0.909 1.097,-0.956 3.141,-0.956 31.502,-0.956 32.962,-2.416 33.742,-2.416 34.211,-1.948 34.211,-0.226 34.11,-0.125 pad.34@34.091,-0.125
el271: E1.276 pad.34@34.241,-0.125 U1.G21 | length 36.1
  metal 2 w0.012: pad.34@34.241,-0.125 E1.276@34.241,-0.106
  metal1 w0.005: U1.G21@1.05,-1.049 1.097,-1.096 31.486,-1.096 32.917,-2.526 33.788,-2.526 34.361,-1.953 34.361,-0.226 34.26,-0.125 pad.34@34.241,-0.125
el272: E1.323 pad.34@34.391,-0.425 U1.G22 | length 35.9
  metal 2 w0.012: pad.34@34.391,-0.425 E1.323@34.391,-0.406
  metal1 w0.005: U1.G22@1.05,-1.189 1.097,-1.236 3.141,-1.236 ; 3.145,-1.236 30.141,-1.236 31.498,-1.236 32.878,-2.616 33.825,-2.616 34.491,-1.951 34.491,-0.506 34.41,-0.425 pad.34@34.391,-0.425
el273: E1.370 pad.34@34.541,-0.725 U1.G23 | length 35.7
  metal 2 w0.012: pad.34@34.541,-0.725 E1.370@34.541,-0.706
  metal1 w0.005: U1.G23@1.05,-1.329 1.097,-1.376 31.511,-1.376 32.841,-2.706 33.862,-2.706 34.621,-1.948 34.621,-0.786 34.56,-0.725 pad.34@34.541,-0.725
el274: E1.371 pad.34@34.691,-0.725 U1.G24 | length 35.9
  metal 2 w0.012: pad.34@34.691,-0.725 E1.371@34.691,-0.706
  metal1 w0.005: U1.G24@1.05,-1.469 1.097,-1.516 3.141,-1.516 30.141,-1.516 31.495,-1.516 32.795,-2.816 33.908,-2.816 34.771,-1.953 34.771,-0.786 34.71,-0.725 pad.34@34.691,-0.725
el275: E1.372 pad.34@34.841,-0.725 U1.G25 | length 36.1
  metal 2 w0.012: pad.34@34.841,-0.725 E1.372@34.841,-0.706
  metal1 w0.005: U1.G25@1.05,-1.609 1.097,-1.656 31.477,-1.656 32.747,-2.926 33.954,-2.926 34.921,-1.959 34.921,-0.786 34.86,-0.725 pad.34@34.841,-0.725
el276: E1.502 pad.34@34.241,-1.625 U1.H20 | length 34.5
  metal 2 w0.012: pad.34@34.241,-1.625 E1.502@34.241,-1.606
  metal1 w0.005: U1.H20@0.91,-0.909 0.967,-0.966 31.498,-0.966 32.958,-2.426 33.746,-2.426 34.261,-1.912 34.261,-1.645 pad.34@34.241,-1.625
el277: E1.503 pad.34@34.391,-1.625 U1.H21 | length 34.7
  metal 2 w0.012: pad.34@34.391,-1.625 E1.503@34.391,-1.606
  metal1 w0.005: U1.H21@0.91,-1.049 0.967,-1.106 3.141,-1.106 31.481,-1.106 32.911,-2.536 33.792,-2.536 34.411,-1.917 34.411,-1.645 pad.34@34.391,-1.625
el278: E1.300 pad.34@34.391,-0.275 U1.H22 | length 36.2
  metal 2 w0.012: pad.34@34.391,-0.275 E1.300@34.391,-0.256
  metal1 w0.005: U1.H22@0.91,-1.189 0.967,-1.246 3.141,-1.246 ; 3.145,-1.246 30.141,-1.246 31.494,-1.246 32.874,-2.626 33.829,-2.626 34.501,-1.955 34.501,-0.366 34.41,-0.275 pad.34@34.391,-0.275
el279: E1.347 pad.34@34.541,-0.575 U1.H23 | length 36.1
  metal 2 w0.012: pad.34@34.541,-0.575 E1.347@34.541,-0.556
  metal1 w0.005: U1.H23@0.91,-1.329 0.967,-1.386 31.507,-1.386 32.837,-2.716 33.867,-2.716 34.631,-1.952 34.631,-0.646 34.56,-0.575 pad.34@34.541,-0.575
el280: E1.348 pad.34@34.691,-0.575 U1.H24 | length 36.2
  metal 2 w0.012: pad.34@34.691,-0.575 E1.348@34.691,-0.556
  metal1 w0.005: U1.H24@0.91,-1.469 0.967,-1.526 3.141,-1.526 30.141,-1.526 31.491,-1.526 32.791,-2.826 33.912,-2.826 34.781,-1.958 34.781,-0.646 34.71,-0.575 pad.34@34.691,-0.575
el281: E1.349 pad.34@34.841,-0.575 U1.H25 | length 36.4
  metal 2 w0.012: pad.34@34.841,-0.575 E1.349@34.841,-0.556
  metal1 w0.005: U1.H25@0.91,-1.609 0.967,-1.666 31.473,-1.666 32.743,-2.936 33.958,-2.936 34.931,-1.963 34.931,-0.646 34.86,-0.575 pad.34@34.841,-0.575
el282: E1.482 pad.34@34.241,-1.475 U1.J20 | length 34.8
  metal 2 w0.012: pad.34@34.241,-1.475 E1.482@34.241,-1.456
  metal1 w0.005: U1.J20@0.77,-0.909 0.837,-0.976 30.141,-0.976 31.494,-0.976 32.954,-2.436 33.751,-2.436 34.271,-1.916 34.271,-1.505 pad.34@34.241,-1.475
el283: E1.483 pad.34@34.391,-1.475 U1.J21 | length 35
  metal 2 w0.012: pad.34@34.391,-1.475 E1.483@34.391,-1.456
  metal1 w0.005: U1.J21@0.77,-1.049 0.837,-1.116 3.141,-1.116 31.477,-1.116 32.907,-2.546 33.796,-2.546 34.421,-1.922 34.421,-1.505 pad.34@34.391,-1.475
el284: E1.277 pad.34@34.391,-0.125 U1.J22 | length 36.5
  metal 2 w0.012: pad.34@34.391,-0.125 E1.277@34.391,-0.106
  metal1 w0.005: U1.J22@0.77,-1.189 0.837,-1.256 31.49,-1.256 32.87,-2.636 33.833,-2.636 34.511,-1.959 34.511,-0.226 34.41,-0.125 pad.34@34.391,-0.125
el285: E1.324 pad.34@34.541,-0.425 U1.J23 | length 36.4
  metal 2 w0.012: pad.34@34.541,-0.425 E1.324@34.541,-0.406
  metal1 w0.005: U1.J23@0.77,-1.329 0.837,-1.396 30.141,-1.396 31.502,-1.396 32.832,-2.726 33.871,-2.726 34.641,-1.956 34.641,-0.506 34.56,-0.425 pad.34@34.541,-0.425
